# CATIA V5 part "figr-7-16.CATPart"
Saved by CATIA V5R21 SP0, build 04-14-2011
Part number: Part2
Bounding box of the stored display mesh (mm): x -50 to 50, y -65 to 65, z 0 to 28
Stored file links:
  D:\CATIA V5R21 E-RESOURCES\CATIA-V5R21\catia-v5r21-prt\c07-catia-v5r20-prt\c07-catia-v5r21-figr-7-16.CATPart
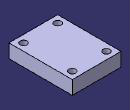
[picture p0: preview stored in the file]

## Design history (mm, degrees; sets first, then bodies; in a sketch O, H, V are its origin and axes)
Body1 (main body)
  Sketch1 on xy-plane, origin (0, 0, 0), H (1, 0, 0), V (0, 1, 0)
    line L1 (-50, 65) -> (50, 65)
    line L2 (50, 65) -> (50, -65)
    line L3 (50, -65) -> (-50, -65)
    line L4 (-50, -65) -> (-50, 65)
    axis line L5 (50, -65) -> (-50, 65)
    length L3 = 100
    length L2 = 130
    horizontal: L1 H, L3 H
    vertical: L2 V, L4 V
    midpoint: O L5
  Pad1: profile Sketch1, direction (0, 0, 1), length 28
  Sketch2 on face of Pad1, origin (25.9302, -33.7092, 28), H (1, 0, 0), V (0, 1, 0)
    point P1 (9.0698, -16.2908)
    reference projected line E1 (-75.9302, -31.2908) -> (24.0698, -31.2908) from edge [face of Pad1 | face of Pad1]
    reference projected line E2 (24.0698, -31.2908) -> (24.0698, 98.7092) from edge [face of Pad1 | face of Pad1]
    distance P1 E1 = 15
    distance P1 E2 = 15
  Hole1: placed by Sketch2, at (35, -50, 28) direction (0, 0, -1), diameter 14, through (limit type 3)
  RectPattern1: of Hole1, direction 1 instances 2, spacing 100, along edge [face of Pad1 | face of Pad1], direction 2 instances 2, spacing 70, along edge [face of Pad1 | face of Pad1]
